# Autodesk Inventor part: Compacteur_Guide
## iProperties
MajorVersion: 11
MinorVersion: 1
Created: 2008-12
Part Number: Compacteur_Guide
Document SubType Name: Modeling
Designer: claivier
Material: Acier galvanisé
Author: claivier
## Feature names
1. Extrusion1
2. Extrusion2
3. Extrusion3
4. Extrusion4
5. Perçage1 [Hole]
6. Extrusion5
7. Chanfrein1 [Chamfer]
8. Miroir1 [Mirror]
9. Perçage2 [Hole]
10. Extrusion6
11. Perçage3 [Hole]
12. Miroir2 [Mirror]
